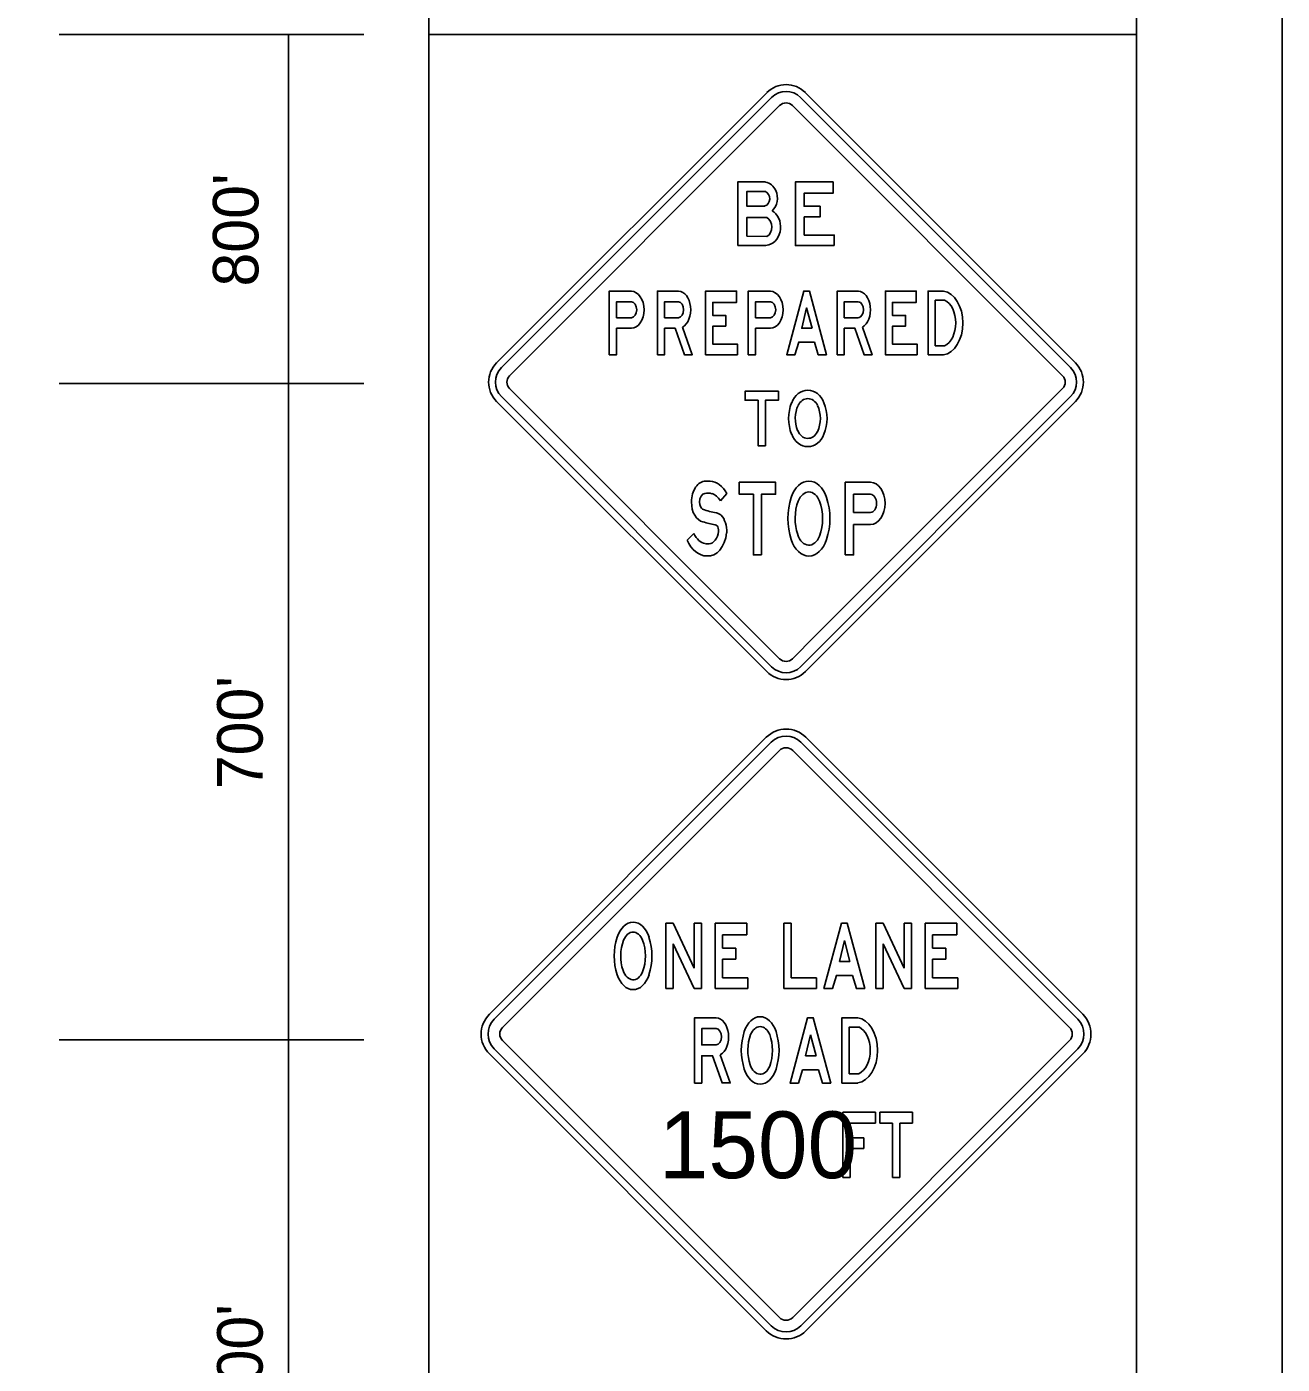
# Model space of a CAD drawing. Extents: x 21.7 to 29.1, y 5.9 to 16.2.
# Drawn here: x 27.437 to 29.094, y 9.44 to 11.205 of the extents above; entities that cross this region are included whole.
import ezdxf

# ---------------------------------------------------------------- set-up
doc = ezdxf.new("R2010")
doc.units = 0
for name, color, linetype in [('BORD-LINE', 7, 'Continuous'), ('C-SIGN-FACE-N', 7, 'Continuous'), ('DETL-DIMS', 7, 'Continuous'), ('DETL-LINE', 7, 'Continuous'), ('DETL-NOTE', 7, 'Continuous')]:
    doc.layers.add(name, color=color, linetype=linetype)

msp = doc.modelspace()

# ---------------------------------------------------------------- linework, layer by layer
at = {"layer": 'BORD-LINE'}
msp.add_lwpolyline([(21.7194, 16.2106), (29.0936, 16.2106), (29.0936, 5.8575), (21.7194, 5.8575)], close=True, dxfattribs=at)
at = {"layer": 'C-SIGN-FACE-N'}
for p, q in [((28.4135, 11.1177), (28.0571, 10.7614)), ((28.8208, 10.7614), (28.4644, 11.1177)), ((28.4199, 11.1114), (28.0635, 10.755)), ((28.4305, 11.1008), (28.0741, 10.7444)), ((28.8038, 10.7444), (28.4474, 11.1008)), ((28.8144, 10.755), (28.458, 11.1114)), ((28.4111, 10.9682), (28.4111, 10.9682)), ((28.4138, 10.9282), (28.4138, 10.9282)), ((28.4305, 10.371), (28.0741, 10.7274)), ((28.4135, 10.3541), (28.0571, 10.7105)), ((28.4199, 10.3604), (28.0635, 10.7168)), ((28.8208, 10.7105), (28.4644, 10.3541)), ((28.3523, 10.5794), (28.3609, 10.589)), ((28.3174, 10.5361), (28.3084, 10.5275)), ((28.4544, 10.5346), (28.4543, 10.5348)), ((28.4129, 10.2674), (28.0475, 9.902)), ((28.8304, 9.902), (28.4651, 10.2674)), ((28.2899, 10.022), (28.2802, 10.022)), ((28.2802, 10.022), (28.2802, 9.9359)), ((28.3176, 9.9628), (28.2899, 10.022)), ((28.3273, 10.022), (28.3176, 10.022)), ((28.3176, 10.022), (28.3176, 9.9628)), ((28.3273, 9.9359), (28.3273, 10.022)), ((28.3454, 10.022), (28.3872, 10.022)), ((28.3454, 9.9359), (28.3454, 10.022)), ((28.3872, 10.022), (28.3872, 10.0067)), ((28.4362, 10.022), (28.4455, 10.022)), ((28.4362, 9.9359), (28.4362, 10.022)), ((28.4455, 10.022), (28.4455, 9.9499)), ((28.5671, 10.022), (28.5574, 10.022)), ((28.5574, 10.022), (28.5574, 9.9359)), ((28.5947, 9.9628), (28.5671, 10.022)), ((28.6045, 10.022), (28.5947, 10.022)), ((28.5947, 10.022), (28.5947, 9.9628)), ((28.6045, 9.9359), (28.6045, 10.022)), ((28.6226, 10.022), (28.6644, 10.022)), ((28.6226, 9.9359), (28.6226, 10.022)), ((28.6644, 10.022), (28.6644, 10.0067)), ((28.3872, 10.0067), (28.3549, 10.0067)), ((28.3549, 10.0067), (28.3549, 9.989)), ((28.6644, 10.0067), (28.6321, 10.0067)), ((28.6321, 10.0067), (28.6321, 9.989)), ((28.2899, 9.9359), (28.2899, 9.9951)), ((28.2899, 9.9951), (28.3176, 9.9359)), ((28.3549, 9.989), (28.3726, 9.989)), ((28.3726, 9.989), (28.3726, 9.9747)), ((28.5094, 9.9718), (28.5159, 9.9993)), ((28.5159, 9.9993), (28.5233, 9.9718)), ((28.5671, 9.9359), (28.5671, 9.9951)), ((28.5671, 9.9951), (28.5947, 9.9359)), ((28.6321, 9.989), (28.6498, 9.989)), ((28.6498, 9.989), (28.6498, 9.9747)), ((28.3726, 9.9747), (28.3552, 9.9747)), ((28.3552, 9.9747), (28.3552, 9.9502)), ((28.5233, 9.9718), (28.5094, 9.9718)), ((28.6498, 9.9747), (28.6323, 9.9747)), ((28.6323, 9.9747), (28.6323, 9.9502)), ((28.5264, 9.9532), (28.5265, 9.9532)), ((28.5264, 9.9532), (28.5265, 9.9532)), ((28.2802, 9.9359), (28.2899, 9.9359)), ((28.3176, 9.9359), (28.3273, 9.9359)), ((28.3885, 9.9359), (28.3454, 9.9359)), ((28.3552, 9.9502), (28.3885, 9.9502)), ((28.3885, 9.9502), (28.3885, 9.9359)), ((28.4793, 9.9359), (28.4362, 9.9359)), ((28.4455, 9.9499), (28.4793, 9.9499)), ((28.4793, 9.9499), (28.4793, 9.9359)), ((28.5574, 9.9359), (28.5671, 9.9359)), ((28.5947, 9.9359), (28.6045, 9.9359)), ((28.6657, 9.9359), (28.6226, 9.9359)), ((28.6323, 9.9502), (28.6657, 9.9502)), ((28.6657, 9.9502), (28.6657, 9.9359)), ((28.4646, 9.8472), (28.4711, 9.8747)), ((28.4711, 9.8747), (28.4785, 9.8472)), ((28.4129, 9.4845), (28.0475, 9.8498)), ((28.4785, 9.8472), (28.4646, 9.8472)), ((28.8304, 9.8498), (28.4651, 9.4845)), ((28.4816, 9.8286), (28.4817, 9.8286)), ((28.4816, 9.8286), (28.4817, 9.8286)), ((28.5138, 9.7729), (28.5569, 9.7729)), ((28.5138, 9.6868), (28.5138, 9.7729)), ((28.5569, 9.7582), (28.5237, 9.7582)), ((28.5237, 9.7582), (28.5237, 9.7392)), ((28.5569, 9.7729), (28.5569, 9.7582)), ((28.5627, 9.7729), (28.6058, 9.7729)), ((28.6058, 9.7729), (28.5627, 9.7729)), ((28.6058, 9.7729), (28.5627, 9.7729)), ((28.5627, 9.7729), (28.5627, 9.7585)), ((28.5627, 9.7585), (28.5795, 9.7585)), ((28.5795, 9.7585), (28.5795, 9.6868)), ((28.5891, 9.6868), (28.5891, 9.7585)), ((28.5891, 9.7585), (28.6058, 9.7585)), ((28.6058, 9.7585), (28.6058, 9.7729)), ((28.5237, 9.7392), (28.5416, 9.7392)), ((28.5416, 9.7392), (28.5416, 9.7251)), ((28.5416, 9.7251), (28.5237, 9.7251)), ((28.5237, 9.7251), (28.5237, 9.6868)), ((28.5237, 9.6868), (28.5138, 9.6868)), ((28.5795, 9.6868), (28.5891, 9.6868))]:
    msp.add_line(p, q, dxfattribs=at)
for points in [[(28.4199, 11.1114), (28.0635, 10.755)], [(28.0741, 10.7444), (28.4305, 11.1008)], [(28.4474, 11.1008), (28.8038, 10.7444)], [(28.8144, 10.755), (28.458, 11.1114)], [(28.4119, 10.9999), (28.3753, 10.9999), (28.3753, 10.916)], [(28.4111, 10.9682), (28.3871, 10.9682), (28.3871, 10.9872), (28.4119, 10.9872)], [(28.3871, 10.9283), (28.3871, 10.953), (28.4137, 10.9529)], [(28.4138, 10.9282), (28.3871, 10.9283)], [(28.3753, 10.916), (28.4052, 10.9159)], [(28.2349, 10.8559), (28.2154, 10.8559), (28.2057, 10.8559), (28.2057, 10.7719)], [(28.2972, 10.8559), (28.2786, 10.8559), (28.2693, 10.8559), (28.2693, 10.7719)], [(28.4183, 10.8559), (28.3988, 10.8559), (28.3891, 10.8559), (28.3891, 10.7719)], [(28.5343, 10.8559), (28.5158, 10.8559), (28.5065, 10.8559), (28.5065, 10.7719)], [(28.6467, 10.8559), (28.6263, 10.8559), (28.6263, 10.7719)], [(28.2349, 10.8209), (28.2154, 10.8209), (28.2154, 10.8419), (28.2349, 10.8419)], [(28.2972, 10.8209), (28.2786, 10.8209), (28.2786, 10.8419), (28.2972, 10.8419)], [(28.4183, 10.8209), (28.3988, 10.8209), (28.3988, 10.8419), (28.4183, 10.8419)], [(28.5158, 10.8209), (28.5158, 10.8419), (28.5343, 10.8419)], [(28.6357, 10.7838), (28.6357, 10.844), (28.6481, 10.844)], [(28.5343, 10.8209), (28.5158, 10.8209)], [(28.2057, 10.7719), (28.2154, 10.7719), (28.2154, 10.8069), (28.2349, 10.8069)], [(28.2693, 10.7719), (28.2786, 10.7719), (28.2786, 10.8069), (28.2925, 10.8069), (28.3048, 10.7721), (28.3152, 10.7721), (28.3024, 10.8083)], [(28.3891, 10.7719), (28.3988, 10.7719), (28.3988, 10.8069), (28.4183, 10.8069)], [(28.5065, 10.7719), (28.5158, 10.7719), (28.5158, 10.8069), (28.5297, 10.8069), (28.542, 10.7721), (28.5524, 10.7721), (28.5396, 10.8083)], [(28.6481, 10.7838), (28.6357, 10.7838)], [(28.6263, 10.7719), (28.6467, 10.7719)], [(28.4305, 10.371), (28.0741, 10.7274), (28.0741, 10.7274)], [(28.8038, 10.7274), (28.4775, 10.4011), (28.4474, 10.371)], [(28.0635, 10.7168), (28.4199, 10.3604)], [(28.458, 10.3604), (28.8144, 10.7168)], [(28.5504, 10.6039), (28.5281, 10.6039), (28.517, 10.6039), (28.517, 10.5079)], [(28.5281, 10.5639), (28.5281, 10.5879), (28.5504, 10.5879)], [(28.5504, 10.5639), (28.5281, 10.5639)], [(28.517, 10.5079), (28.5281, 10.5079), (28.5281, 10.5479), (28.5504, 10.5479)], [(28.4194, 10.2608), (28.054, 9.8955)], [(28.8239, 9.8955), (28.4585, 10.2608)], [(28.0649, 9.8846), (28.4303, 10.25)], [(28.4477, 10.25), (28.813, 9.8846)], [(28.5265, 9.9532), (28.5055, 9.9532), (28.5001, 9.9359), (28.489, 9.9359), (28.5122, 10.022), (28.5197, 10.022), (28.5428, 9.9359), (28.5317, 9.9359), (28.5264, 9.9532)], [(28.3183, 9.8113), (28.3183, 9.8974), (28.3278, 9.8974), (28.3468, 9.8974)], [(28.3468, 9.8615), (28.3278, 9.8615), (28.3278, 9.8831), (28.3468, 9.8831)], [(28.4817, 9.8286), (28.4607, 9.8286), (28.4553, 9.8113), (28.4442, 9.8113), (28.4674, 9.8974), (28.4749, 9.8974), (28.498, 9.8113), (28.4869, 9.8113), (28.4816, 9.8286)], [(28.5335, 9.8113), (28.5126, 9.8113), (28.5126, 9.8974), (28.5335, 9.8974)], [(28.535, 9.8852), (28.5223, 9.8852), (28.5223, 9.8235), (28.535, 9.8235)], [(28.4303, 9.5019), (28.0649, 9.8672)], [(28.813, 9.8672), (28.4477, 9.5019)], [(28.054, 9.8563), (28.4194, 9.491)], [(28.3522, 9.8487), (28.3653, 9.8115), (28.3546, 9.8115), (28.342, 9.8472), (28.3278, 9.8472), (28.3278, 9.8113), (28.3183, 9.8113)], [(28.4585, 9.491), (28.8239, 9.8563)]]:
    msp.add_lwpolyline(points, dxfattribs=at)
for points in [[(28.5026, 10.9159), (28.5026, 10.9299), (28.463, 10.9299), (28.463, 10.9538), (28.4838, 10.9538), (28.4838, 10.9678), (28.4627, 10.9678), (28.4627, 10.985), (28.5011, 10.985), (28.5011, 10.9999), (28.4514, 10.9999), (28.4514, 10.9159)], [(28.3749, 10.7719), (28.3749, 10.7859), (28.3424, 10.7859), (28.3424, 10.8098), (28.3595, 10.8098), (28.3595, 10.8238), (28.3422, 10.8238), (28.3422, 10.841), (28.3737, 10.841), (28.3737, 10.8559), (28.3329, 10.8559), (28.3329, 10.7719)], [(28.4763, 10.7888), (28.4815, 10.7719), (28.4923, 10.7719), (28.4697, 10.8559), (28.4624, 10.8559), (28.4398, 10.7719), (28.4506, 10.7719), (28.4558, 10.7888)], [(28.6121, 10.7719), (28.6121, 10.7859), (28.5796, 10.7859), (28.5796, 10.8098), (28.5967, 10.8098), (28.5967, 10.8238), (28.5793, 10.8238), (28.5793, 10.841), (28.6108, 10.841), (28.6108, 10.8559), (28.5701, 10.8559), (28.5701, 10.7719)], [(28.4732, 10.807), (28.4596, 10.807), (28.466, 10.8338)], [(28.4118, 10.6519), (28.402, 10.6519), (28.402, 10.7119), (28.3849, 10.7119), (28.3849, 10.7239), (28.4288, 10.7239), (28.4288, 10.7119), (28.4118, 10.7119)], [(28.4064, 10.5079), (28.3958, 10.5079), (28.3958, 10.5879), (28.3771, 10.5879), (28.3771, 10.6039), (28.4251, 10.6039), (28.4251, 10.5879), (28.4064, 10.5879)]]:
    msp.add_lwpolyline(points, close=True, dxfattribs=at)
for centre, radius, start, end in [((28.439, 11.0923), 0.036, 45, 135), ((28.439, 11.0923), 0.027, 45, 135), ((28.439, 11.0923), 0.027, 45, 135), ((28.439, 11.0923), 0.012, 45, 135), ((28.439, 11.0923), 0.012, 45, 135), ((28.0826, 10.7359), 0.036, 135, 225), ((28.0826, 10.7359), 0.027, 135, 225), ((28.0826, 10.7359), 0.027, 135, 225), ((28.7953, 10.7359), 0.027, 315, 45), ((28.7953, 10.7359), 0.027, 315, 45), ((28.7953, 10.7359), 0.036, 315, 45), ((28.0826, 10.7359), 0.012, 135, 224.9596), ((28.0826, 10.7359), 0.012, 135, 224.9596), ((28.7953, 10.7359), 0.012, 315, 45), ((28.7953, 10.7359), 0.012, 315, 45), ((28.439, 10.3795), 0.027, 225, 315), ((28.439, 10.3795), 0.027, 225, 315), ((28.439, 10.3795), 0.012, 225, 315), ((28.439, 10.3795), 0.012, 225, 315), ((28.439, 10.3795), 0.036, 225, 315), ((28.439, 10.2413), 0.0369, 45, 135), ((28.439, 10.2413), 0.0277, 45, 135), ((28.439, 10.2413), 0.0123, 45, 135), ((28.0736, 9.8759), 0.0369, 135, 225), ((28.8043, 9.8759), 0.0369, 315, 45), ((28.0736, 9.8759), 0.0277, 135, 225), ((28.0736, 9.8759), 0.0123, 135, 225), ((28.8043, 9.8759), 0.0123, 315, 45), ((28.8043, 9.8759), 0.0277, 315, 45), ((28.439, 9.5106), 0.0123, 225, 315), ((28.439, 9.5106), 0.0369, 225, 315), ((28.439, 9.5106), 0.0277, 225, 315)]:
    msp.add_arc(centre, radius, start, end, dxfattribs=at)
for centre, major_axis, ratio, start_param, end_param in [((28.4096, 10.9789), (0, 0.0211), 0.839466, 5.185175, 6.153935), ((28.409, 10.9779), (0, 0.00997), 0.839466, 3.388797, 5.931995), ((28.4104, 10.9785), (0, 0.0205), 0.839466, 3.776083, 5.22325), ((28.4115, 10.9405), (0, 0.0241), 0.839466, 3.374344, 5.817162), ((28.4089, 10.9405), (0, 0.0136), 0.839466, 3.582433, 5.852916), ((28.4058, 10.9587), (0, 0.0428), 0.839466, 3.125363, 3.212577), ((28.4042, 11.0077), (0, 0.0919), 0.839466, 3.195342, 3.296884), ((28.2346, 10.8314), (0, 0.0245), 0.693489, 3.155423, 6.269038), ((28.2969, 10.8314), (0, 0.0245), 0.661997, 3.487455, 6.269173), ((28.418, 10.8314), (0, 0.0245), 0.693489, 3.155423, 6.269132), ((28.5341, 10.8314), (0, 0.0245), 0.661997, 3.487757, 6.26934), ((28.6441, 10.8139), (0, 0.0422), 0.666086, 3.232672, 6.192098), ((28.2346, 10.8314), (0, 0.0105), 0.693489, 3.174143, 6.249901), ((28.2969, 10.8314), (0, 0.0105), 0.661997, 3.174143, 6.250249), ((28.418, 10.8314), (0, 0.0105), 0.693489, 3.174143, 6.25012), ((28.5341, 10.8314), (0, 0.0105), 0.661997, 3.174143, 6.250635), ((28.6418, 10.8139), (0, 0.0316), 0.666086, 3.446507, 5.978172), ((28.4677, 10.6959), (0, 0.0292), 0.812335, 5.167056, 7.399315), ((28.4677, 10.6959), (0, 0.0183), 0.812335, 5.251232, 7.315139), ((28.4796, 10.6879), (0, 0.0459), 0.812335, 1.101522, 2.04007), ((28.4796, 10.6879), (0, 0.0351), 0.812335, 1.053076, 2.040122), ((28.4557, 10.6879), (0, 0.0351), 0.812335, 4.194619, 5.230159), ((28.4557, 10.6879), (0, 0.0459), 0.812335, 4.243115, 5.181663), ((28.4677, 10.68), (0, 0.0292), 0.812335, 2.025463, 3.141593), ((28.4677, 10.68), (0, 0.0183), 0.812335, 2.025521, 3.099563), ((28.4677, 10.68), (0, 0.0183), 0.812335, 3.099563, 4.173604), ((28.4677, 10.68), (0, 0.0292), 0.812335, 3.141593, 4.257722), ((28.3325, 10.5776), (0, 0.0276), 0.66615, 6.26385, 7.849768), ((28.3357, 10.5606), (0, 0.0448), 0.66615, 6.185083, 6.379154), ((28.3375, 10.5592), (0, 0.0461), 0.66615, 5.417783, 6.245524), ((28.4691, 10.5665), (0, 0.0389), 0.667963, 5.167056, 7.399315), ((28.5501, 10.5759), (0, 0.028), 0.693489, 3.155423, 6.268798), ((28.3325, 10.5776), (0, 0.0116), 0.66615, 0.077411, 1.57362), ((28.3358, 10.5543), (0, 0.0353), 0.66615, 6.063078, 6.446889), ((28.3375, 10.5592), (0, 0.0301), 0.66615, 5.451674, 6.113321), ((28.4691, 10.5665), (0, 0.0245), 0.667963, 5.251232, 7.315139), ((28.5501, 10.5759), (0, 0.012), 0.693489, 3.174143, 6.250635), ((28.3315, 10.5774), (0, 0.026), 0.66615, 1.5566, 3.019028), ((28.3315, 10.5774), (0, 0.01), 0.66615, 1.548818, 2.74578), ((28.4822, 10.5559), (0, 0.0612), 0.667963, 1.101522, 2.04007), ((28.4822, 10.5559), (0, 0.0468), 0.667963, 1.053076, 2.040122), ((28.4559, 10.5559), (0, 0.0468), 0.667963, 4.194619, 5.230159), ((28.4559, 10.5559), (0, 0.0612), 0.667963, 4.243115, 5.181663), ((28.3588, 10.7526), (0, 0.1898), 0.66615, 2.903022, 3.048485), ((28.3588, 10.7526), (0, 0.2058), 0.66615, 2.925313, 3.043429), ((28.3406, 10.5178), (0, 0.0467), 0.66615, 5.858321, 6.074573), ((28.343, 10.539), (0, 0.0265), 0.66615, 4.646351, 5.651125), ((28.3346, 10.5541), (0, 0.0315), 0.66615, 2.178648, 3.018166), ((28.3367, 10.5427), (0, 0.0362), 0.66615, 3.054011, 4.562492), ((28.3367, 10.5427), (0, 0.0202), 0.66615, 3.202031, 4.526443), ((28.3406, 10.5178), (0, 0.0307), 0.66615, 5.919654, 6.048202), ((28.343, 10.539), (0, 0.0105), 0.66615, 4.704762, 5.511974), ((28.4691, 10.5453), (0, 0.0245), 0.667963, 2.025521, 4.173604), ((28.3346, 10.5541), (0, 0.0475), 0.66615, 2.164837, 3.141505), ((28.3359, 10.5623), (0, 0.0399), 0.66615, 2.996497, 3.204075), ((28.4691, 10.5453), (0, 0.0389), 0.667963, 2.025463, 3.141593), ((28.4691, 10.5453), (0, 0.0389), 0.667963, 3.141593, 4.257722), ((28.2372, 9.9885), (0, 0.0349), 0.667963, 5.167056, 7.399315), ((28.2489, 9.9789), (0, 0.0549), 0.667963, 1.101522, 2.04007), ((28.2372, 9.9885), (0, 0.0219), 0.667963, 5.251232, 7.315139), ((28.2254, 9.9789), (0, 0.0549), 0.667963, 4.243115, 5.181663), ((28.2489, 9.9789), (0, 0.042), 0.667963, 1.053076, 2.040122), ((28.2254, 9.9789), (0, 0.042), 0.667963, 4.194619, 5.230159), ((28.2372, 9.9694), (0, 0.0349), 0.667963, 2.025463, 4.257722), ((28.2372, 9.9694), (0, 0.0219), 0.667963, 2.025521, 4.173604), ((28.4048, 9.8639), (0, 0.0349), 0.667963, 5.167056, 7.399315), ((28.3466, 9.8723), (0, 0.0251), 0.661997, 3.487455, 6.26934), ((28.3466, 9.8723), (0, 0.0108), 0.661997, 3.174143, 6.250635), ((28.4048, 9.8639), (0, 0.0219), 0.667963, 5.251232, 7.315139), ((28.5309, 9.8544), (0, 0.0432), 0.666086, 3.232672, 6.192106), ((28.5285, 9.8544), (0, 0.0324), 0.666086, 3.446507, 5.978271), ((28.4166, 9.8544), (0, 0.0549), 0.667963, 1.101522, 2.04007), ((28.4166, 9.8544), (0, 0.042), 0.667963, 1.053076, 2.040122), ((28.393, 9.8544), (0, 0.042), 0.667963, 4.194619, 5.230159), ((28.393, 9.8544), (0, 0.0549), 0.667963, 4.243115, 5.181663), ((28.4048, 9.8448), (0, 0.0349), 0.667963, 2.025463, 4.257722), ((28.4048, 9.8449), (0, 0.0219), 0.667963, 2.025521, 4.173604)]:
    msp.add_ellipse(centre, major_axis=major_axis, ratio=ratio, start_param=start_param, end_param=end_param, dxfattribs=at)
at = {"layer": 'DETL-DIMS'}
for p, q in [((27.8819, 11.1944), (27.48, 11.1944)), ((27.7826, 11.1944), (27.7826, 10.7339)), ((27.8819, 10.7339), (27.48, 10.7339)), ((27.7826, 10.7339), (27.7826, 9.8681)), ((27.8819, 9.8681), (27.48, 9.8681)), ((27.7826, 9.8681), (27.7826, 9.0023))]:
    msp.add_line(p, q, dxfattribs=at)
at = {"layer": 'DETL-LINE'}
for p, q in [((27.9676, 8.5166), (27.9676, 11.5089)), ((28.9014, 8.5166), (28.9014, 11.5089)), ((28.9014, 11.1944), (27.9676, 11.1944))]:
    msp.add_line(p, q, dxfattribs=at)

# ---------------------------------------------------------------- texts
at = {"layer": 'DETL-NOTE'}
for s, p in [("800'", (27.7428, 10.862)), ("700'", (27.7484, 10.1989)), ("1100'", (27.7484, 9.3258))]:
    msp.add_text(s, height=0.06, rotation=90, dxfattribs=at).set_placement(p)
msp.add_text('1500', height=0.088, dxfattribs=at).set_placement((28.271, 9.6858))

doc.saveas('drawing.dxf')
